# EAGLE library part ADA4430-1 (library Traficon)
Ultralow Power Video Filter with Power-Down
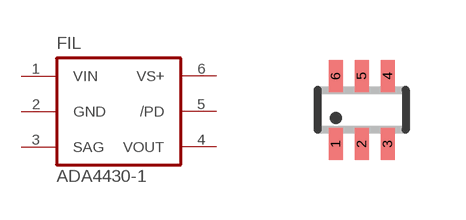
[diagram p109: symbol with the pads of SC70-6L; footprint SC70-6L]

Designator prefix FIL

## ADA4430-1  [SC70-6L]
1  VIN
2  GND
3  SAG
4  VOUT
5  /PD
6  VS+

## Footprint SC70-6L (pad centres in mm)
SC-70 Package
smd 0.35 x 0.8: 1 -0.65,-0.85; 2 0,-0.85; 3 0.65,-0.85; 4 0.65,0.85; 5 0,0.85; 6 -0.65,0.85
